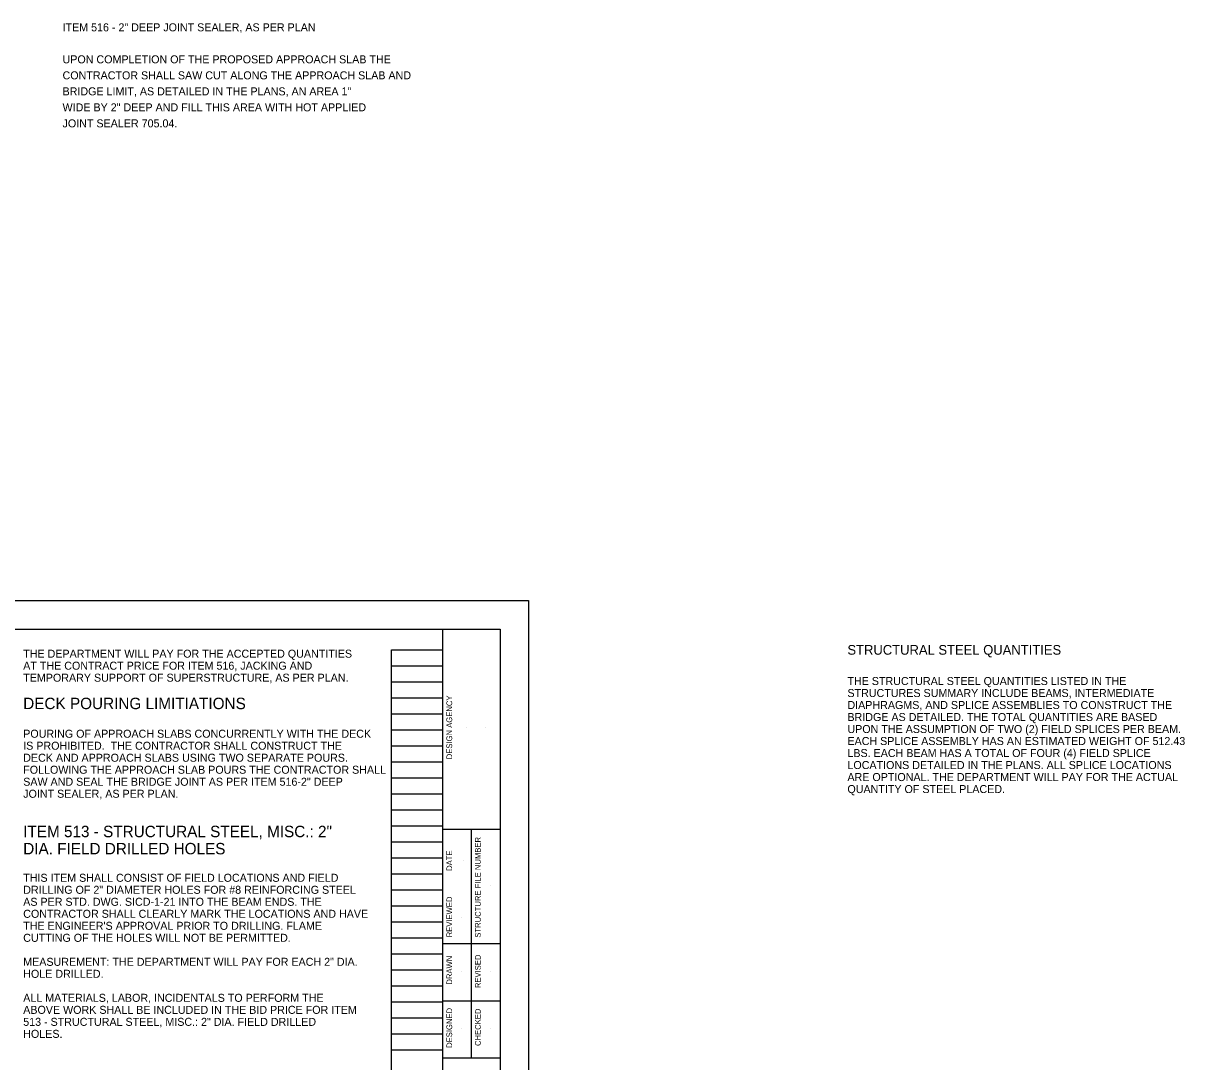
# Model space of a CAD drawing. Extents: x -51.6 to 45.5, y -38.3 to 35.3.
# Drawn here: x 25.16 to 45.48, y 13.93 to 32.1 of the extents above; entities that cross this region are included whole.
import ezdxf

# ---------------------------------------------------------------- set-up
doc = ezdxf.new("R2010")
doc.units = 0
for name, color, linetype in [('BD_P_Text', 7, 'Continuous'), ('SH_Border', 7, 'Continuous'), ('SH_Cut_Line', 7, 'Continuous'), ('SH_Data', 7, 'Continuous'), ('SH_Text', 7, 'Continuous')]:
    doc.layers.add(name, color=color, linetype=linetype)

msp = doc.modelspace()

# ---------------------------------------------------------------- linework, layer by layer
at = {"layer": 'SH_Border'}
for p, q in [((32.5, 0.5), (32.5, 21.5)), ((32.5, 18), (33.5, 18)), ((33, 14), (33, 18)), ((32.5, 16), (33.5, 16)), ((32.5, 15), (33.5, 15)), ((32.5, 14), (33.5, 14))]:
    msp.add_line(p, q, dxfattribs=at)
msp.add_lwpolyline([(2, 21.5), (33.5, 21.5), (33.5, 0.5), (2, 0.5)], close=True, dxfattribs=at)
at = {"layer": 'SH_Cut_Line'}
msp.add_lwpolyline([(0, 22), (34, 22), (34, 0), (0, 0)], close=True, dxfattribs=at)
at = {"layer": 'SH_Data'}
for p, q in [((31.6, 0.98), (31.6, 21.14)), ((31.6, 21.14), (32.5, 21.14)), ((32.5, 0.98), (32.5, 21.14)), ((31.6, 20.86), (32.5, 20.86)), ((31.6, 20.58), (32.5, 20.58)), ((31.6, 20.3), (32.5, 20.3)), ((31.6, 20.02), (32.5, 20.02)), ((31.6, 19.74), (32.5, 19.74)), ((32.921, 19.773), (32.921, 19.773)), ((33.254, 19.773), (33.254, 19.773)), ((31.6, 19.46), (32.5, 19.46)), ((31.6, 19.18), (32.5, 19.18)), ((31.6, 18.9), (32.5, 18.9)), ((31.6, 18.62), (32.5, 18.62)), ((31.6, 18.34), (32.5, 18.34)), ((31.6, 18.06), (32.5, 18.06)), ((31.6, 17.78), (32.5, 17.78)), ((31.6, 17.5), (32.5, 17.5)), ((32.86, 17.449), (32.86, 17.449)), ((31.6, 17.22), (32.5, 17.22)), ((31.6, 16.94), (32.5, 16.94)), ((33.333, 17.009), (33.333, 17.009)), ((31.6, 16.66), (32.5, 16.66)), ((31.6, 16.38), (32.5, 16.38)), ((32.833, 16.447), (32.833, 16.447)), ((31.6, 16.1), (32.5, 16.1)), ((31.6, 15.82), (32.5, 15.82)), ((31.6, 15.54), (32.5, 15.54)), ((32.833, 15.51), (32.833, 15.51)), ((33.333, 15.51), (33.333, 15.51)), ((31.6, 15.26), (32.5, 15.26)), ((31.6, 14.98), (32.5, 14.98)), ((31.6, 14.7), (32.5, 14.7)), ((32.833, 14.51), (32.833, 14.51)), ((33.333, 14.509), (33.333, 14.509)), ((31.6, 14.42), (32.5, 14.42)), ((31.6, 14.14), (32.5, 14.14))]:
    msp.add_line(p, q, dxfattribs=at)

# ---------------------------------------------------------------- texts
at = {"layer": 'BD_P_Text'}
for s, height, p in [('ITEM 516 - 2" DEEP JOINT SEALER, AS PER PLAN', 0.14, (25.848, 31.957)), ('UPON COMPLETION OF THE PROPOSED APPROACH SLAB THE ', 0.14, (25.848, 31.397)), ('CONTRACTOR SHALL SAW CUT ALONG THE APPROACH SLAB AND ', 0.14, (25.848, 31.117)), ('BRIDGE LIMIT, AS DETAILED IN THE PLANS, AN AREA 1" ', 0.14, (25.848, 30.837)), ('WIDE BY 2" DEEP AND FILL THIS AREA WITH HOT APPLIED ', 0.14, (25.848, 30.557)), ('JOINT SEALER 705.04.', 0.14, (25.848, 30.277)), ('DECK POURING LIMITIATIONS', 0.2, (25.16, 20.1)), ('POURING OF APPROACH SLABS CONCURRENTLY WITH THE DECK ', 0.14, (25.16, 19.6)), ('IS PROHIBITED.  THE CONTRACTOR SHALL CONSTRUCT THE ', 0.14, (25.16, 19.39)), ('DECK AND APPROACH SLABS USING TWO SEPARATE POURS.  ', 0.14, (25.16, 19.18)), ('FOLLOWING THE APPROACH SLAB POURS THE CONTRACTOR SHALL ', 0.14, (25.16, 18.97)), ('SAW AND SEAL THE BRIDGE JOINT AS PER ITEM 516-2" DEEP ', 0.14, (25.16, 18.76)), ('JOINT SEALER, AS PER PLAN.', 0.14, (25.16, 18.55))]:
    msp.add_text(s, height=height, dxfattribs=at).set_placement(p)
at = {"layer": 'SH_Data'}
for s, p in [('DESIGN AGENCY', (32.663, 19.224)), ('STRUCTURE FILE NUMBER', (33.163, 16.103)), ('DATE', (32.663, 17.271)), ('REVIEWED', (32.663, 16.108)), ('DRAWN', (32.663, 15.281)), ('REVISED', (33.163, 15.22)), ('DESIGNED', (32.663, 14.175)), ('CHECKED', (33.163, 14.208))]:
    msp.add_text(s, height=0.1, rotation=90, dxfattribs=at).set_placement(p)
at = {"layer": 'SH_Text'}
for s, height, p in [('THE DEPARTMENT WILL PAY FOR THE ACCEPTED QUANTITIES ', 0.14, (25.16, 21)), ('STRUCTURAL STEEL QUANTITIES', 0.17, (39.577, 21.052)), ('AT THE CONTRACT PRICE FOR ITEM 516, JACKING AND ', 0.14, (25.16, 20.79)), ('TEMPORARY SUPPORT OF SUPERSTRUCTURE, AS PER PLAN.', 0.14, (25.16, 20.58)), ('THE STRUCTURAL STEEL QUANTITIES LISTED IN THE ', 0.14, (39.577, 20.522)), ('STRUCTURES SUMMARY INCLUDE BEAMS, INTERMEDIATE ', 0.14, (39.577, 20.312)), ('DIAPHRAGMS, AND SPLICE ASSEMBLIES TO CONSTRUCT THE ', 0.14, (39.577, 20.102)), ('BRIDGE AS DETAILED. THE TOTAL QUANTITIES ARE BASED ', 0.14, (39.577, 19.892)), ('UPON THE ASSUMPTION OF TWO (2) FIELD SPLICES PER BEAM. ', 0.14, (39.577, 19.682)), ('EACH SPLICE ASSEMBLY HAS AN ESTIMATED WEIGHT OF 512.43 ', 0.14, (39.577, 19.472)), ('LBS. EACH BEAM HAS A TOTAL OF FOUR (4) FIELD SPLICE ', 0.14, (39.577, 19.262)), ('LOCATIONS DETAILED IN THE PLANS. ALL SPLICE LOCATIONS ', 0.14, (39.577, 19.052)), ('ARE OPTIONAL. THE DEPARTMENT WILL PAY FOR THE ACTUAL ', 0.14, (39.577, 18.842)), ('QUANTITY OF STEEL PLACED.', 0.14, (39.577, 18.632)), ('ITEM 513 - STRUCTURAL STEEL, MISC.: 2" ', 0.2, (25.16, 17.86)), ('DIA. FIELD DRILLED HOLES', 0.2, (25.16, 17.56)), ('THIS ITEM SHALL CONSIST OF FIELD LOCATIONS AND FIELD ', 0.14, (25.16, 17.08)), ('DRILLING OF 2" DIAMETER HOLES FOR #8 REINFORCING STEEL ', 0.14, (25.16, 16.87)), ('AS PER STD. DWG. SICD-1-21 INTO THE BEAM ENDS. THE ', 0.14, (25.16, 16.66)), ('CONTRACTOR SHALL CLEARLY MARK THE LOCATIONS AND HAVE ', 0.14, (25.16, 16.45)), ("THE ENGINEER'S APPROVAL PRIOR TO DRILLING. FLAME ", 0.14, (25.16, 16.24)), ('CUTTING OF THE HOLES WILL NOT BE PERMITTED.', 0.14, (25.16, 16.03)), ('MEASUREMENT: THE DEPARTMENT WILL PAY FOR EACH 2" DIA. ', 0.14, (25.16, 15.61)), ('HOLE DRILLED.', 0.14, (25.16, 15.4)), ('ALL MATERIALS, LABOR, INCIDENTALS TO PERFORM THE ', 0.14, (25.16, 14.98)), ('ABOVE WORK SHALL BE INCLUDED IN THE BID PRICE FOR ITEM ', 0.14, (25.16, 14.77)), ('513 - STRUCTURAL STEEL, MISC.: 2" DIA. FIELD DRILLED ', 0.14, (25.16, 14.56)), ('HOLES.', 0.14, (25.16, 14.35))]:
    msp.add_text(s, height=height, dxfattribs=at).set_placement(p)

doc.saveas('drawing.dxf')
